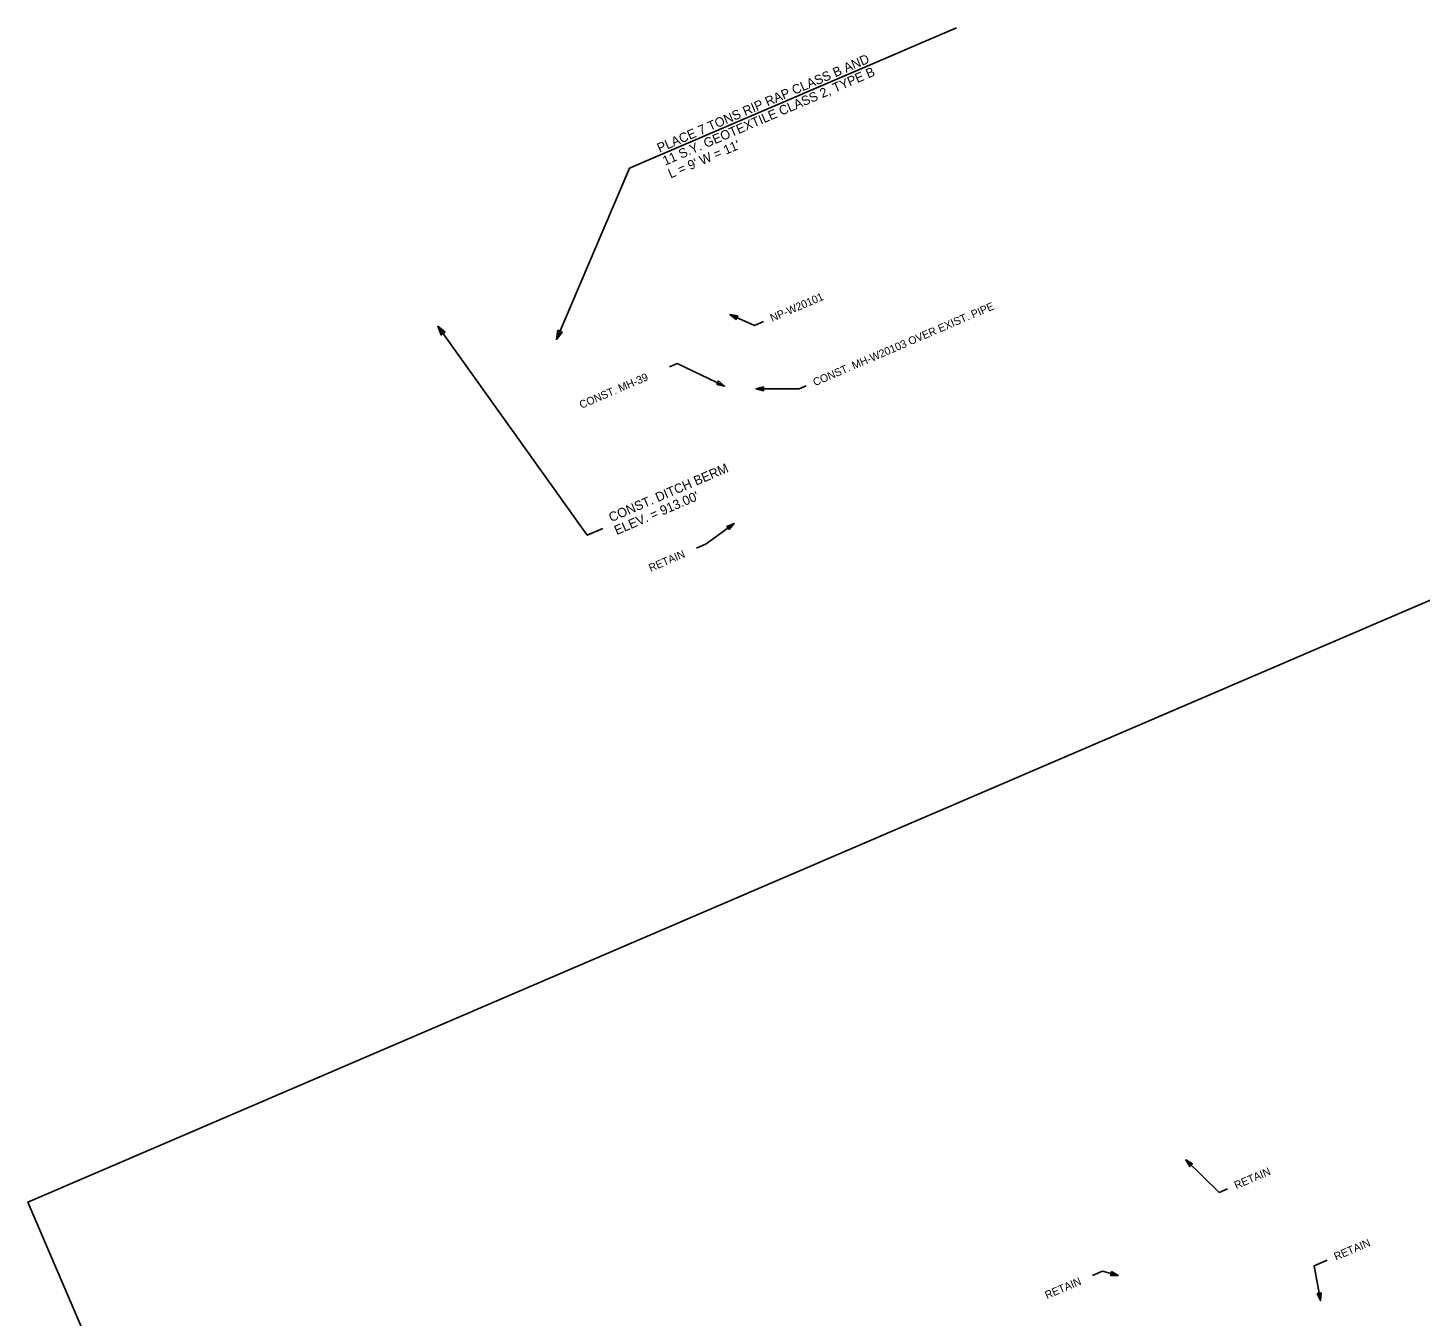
# Model space of a CAD drawing. Extents: x 1621083 to 1622865, y 1102384 to 1104005.
# Drawn here: x 1621083 to 1621976, y 1103179 to 1104005 of the extents above; entities that cross this region are included whole.
import ezdxf

# ---------------------------------------------------------------- set-up
doc = ezdxf.new("R2010")
doc.units = 0
doc.layers.add('Level 8', color=7, linetype='Continuous')
doc.layers.add('RFP', color=7, linetype='Continuous')

msp = doc.modelspace()

# ---------------------------------------------------------------- linework, layer by layer
at = {"layer": 'Level 8'}
msp.add_line((1621678.91, 1104005.46), (1621483.06, 1103921.4), dxfattribs=at)
for points in [[(1621483.06, 1103921.4), (1621469.15, 1103915.43), (1621422.22, 1103805.59)], [(1621555.07, 1103817.12), (1621549.22, 1103814.61), (1621533.58, 1103821.61)], [(1621452.05, 1103684.43), (1621442.04, 1103680.13), (1621346.18, 1103814.08)], [(1621494.69, 1103788.01), (1621499.77, 1103790.19), (1621530.06, 1103775.73)], [(1621582.52, 1103775.91), (1621578.02, 1103773.98), (1621550.31, 1103773.95)], [(1621512.03, 1103671.76), (1621518.34, 1103674.47), (1621536.31, 1103687.5)], [(1621852.75, 1103260.8), (1621847.44, 1103258.52), (1621825.9, 1103279.33)], [(1621916.74, 1103215.09), (1621908.2, 1103211.42), (1621912.28, 1103189.1)], [(1621766.19, 1103205.3), (1621772.48, 1103208), (1621782.59, 1103205.09)]]:
    msp.add_lwpolyline(points, dxfattribs=at)
for points in [[(1621538.52, 1103820.82), (1621533.58, 1103821.61), (1621537.46, 1103818.45)], [(1621350.81, 1103810.27), (1621346.18, 1103814.08), (1621348.29, 1103808.46)], [(1621423.07, 1103811.53), (1621422.22, 1103805.59), (1621425.92, 1103810.31)], [(1621525.15, 1103776.64), (1621530.06, 1103775.73), (1621526.26, 1103778.97)], [(1621555.14, 1103775.25), (1621550.31, 1103773.95), (1621555.15, 1103772.66)], [(1621533.16, 1103683.62), (1621536.31, 1103687.5), (1621531.64, 1103685.71)], [(1621830.27, 1103276.9), (1621825.9, 1103279.33), (1621828.47, 1103275.04)], [(1621777.59, 1103205.18), (1621782.59, 1103205.09), (1621778.3, 1103207.67)], [(1621910.14, 1103193.62), (1621912.28, 1103189.1), (1621912.69, 1103194.09)]]:
    msp.add_lwpolyline(points, close=True, dxfattribs=at)
at = {"layer": 'RFP'}
msp.add_lwpolyline([(1621300.09, 1102746.85), (1621324.02, 1102752.88), (1621344.3, 1102622.52), (1621455.74, 1102384.16), (1622813.61, 1102966.94), (1622454.69, 1103803.24), (1622329.06, 1103749.66), (1622314.99, 1103780.87), (1621083.19, 1103252.2)], close=True, dxfattribs=at)
msp.add_lwpolyline([(1621300.09, 1102746.85), (1621324.02, 1102752.88), (1621344.3, 1102622.52), (1621455.74, 1102384.16), (1622813.61, 1102966.94), (1622454.69, 1103803.24), (1622329.06, 1103749.66), (1622314.99, 1103780.87), (1621083.19, 1103252.2)], close=True, dxfattribs=at)
msp.add_lwpolyline([(1621300.09, 1102746.85), (1621324.02, 1102752.88), (1621344.3, 1102622.52), (1621455.74, 1102384.16), (1622813.61, 1102966.94), (1622454.69, 1103803.24), (1622329.06, 1103749.66), (1622314.99, 1103780.87), (1621083.19, 1103252.2)], close=True, dxfattribs=at)
msp.add_lwpolyline([(1621300.09, 1102746.85), (1621324.02, 1102752.88), (1621344.3, 1102622.52), (1621455.74, 1102384.16), (1622813.61, 1102966.94), (1622454.69, 1103803.24), (1622329.06, 1103749.66), (1622314.99, 1103780.87), (1621083.19, 1103252.2)], close=True, dxfattribs=at)
msp.add_lwpolyline([(1621300.09, 1102746.85), (1621324.02, 1102752.88), (1621344.3, 1102622.52), (1621455.74, 1102384.16), (1622813.61, 1102966.94), (1622454.69, 1103803.24), (1622329.06, 1103749.66), (1622314.99, 1103780.87), (1621083.19, 1103252.2)], close=True, dxfattribs=at)

# ---------------------------------------------------------------- texts
at = {"layer": 'Level 8'}
for s, height, p in [('PLACE 7 TONS RIP RAP CLASS B AND', 6, (1621488.4, 1103925.32)), ('11 S.Y. GEOTEXTILE CLASS 2, TYPE B', 6, (1621491.95, 1103917.05)), ("L = 9' W = 11'", 6, (1621495.5, 1103908.78)), ('NP-W20101', 5, (1621560.65, 1103816.79)), ('CONST. MH-W20103 OVER EXIST. PIPE', 5, (1621588.1, 1103775.58)), ('CONST. MH-39', 5, (1621438.26, 1103761.07)), ('CONST. DITCH BERM', 6, (1621457.39, 1103688.35)), ("ELEV. = 913.00'", 6, (1621460.94, 1103680.08)), ('RETAIN', 5, (1621482.74, 1103656.47)), ('RETAIN', 5, (1621858.33, 1103260.47)), ('RETAIN', 5, (1621922.32, 1103214.76)), ('RETAIN', 5, (1621736.89, 1103190))]:
    msp.add_text(s, height=height, rotation=23.22835, dxfattribs=at).set_placement(p)

doc.saveas('drawing.dxf')
